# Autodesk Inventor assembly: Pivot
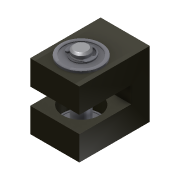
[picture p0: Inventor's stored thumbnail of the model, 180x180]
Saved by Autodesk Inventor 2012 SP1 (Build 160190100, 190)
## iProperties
Created: 2005-12
Part Number: Pivot
Document SubType Name: Assembly
Designer: t_munrn
Author: t_munrn
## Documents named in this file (5)
- D:\AOTC\Autodesk Inventor 2012 Essential for New Users\Autodesk Inventor 2012 Essentials - Project Files\Learning\Workspace\Sub-Assemblies\Pivot.iam
- D:\AOTC\Autodesk Inventor 2012 Essential for New Users\Autodesk Inventor 2012 Essentials - Project Files\Learning\Workspace\Parts\pivot shaft.ipt
- D:\AOTC\Autodesk Inventor 2012 Essential for New Users\Autodesk Inventor 2012 Essentials - Project Files\Learning\Workspace\Parts\BEARING _5X1_25 FLANGED.ipt
- D:\AOTC\Autodesk Inventor 2012 Essential for New Users\Autodesk Inventor 2012 Essentials - Project Files\Learning\Workspace\Parts\BEARING MOUNT.ipt
- D:\AOTC\Autodesk Inventor 2012 Essential for New Users\Autodesk Inventor 2012 Essentials - Project Files\Learning\Workspace\Libraries\Content Center Files\en-US\12-10.3-12.ipt
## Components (6 placed, 4 different names)
1. BEARING MOUNT:1 — Flush:1, Flush:2, Flush:3, Flush:4
2. pivot shaft:1 — Flush:4, Insert:3, Insert:4
3. BEARING _5X1_25 FLANGED:1
4. BEARING _5X1_25 FLANGED:2
5. 12-10.3-12:1 — Insert:4
6. 12-10.3-12:2 — Insert:3
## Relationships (6: Flush 4, Insert 2)
- Flush:1: BEARING MOUNT:1
- Flush:2: BEARING MOUNT:1
- Flush:3: BEARING MOUNT:1
- Flush:4: BEARING MOUNT:1 ↔ pivot shaft:1
- Insert:3: pivot shaft:1 ↔ 12-10.3-12:2
- Insert:4: pivot shaft:1 ↔ 12-10.3-12:1
